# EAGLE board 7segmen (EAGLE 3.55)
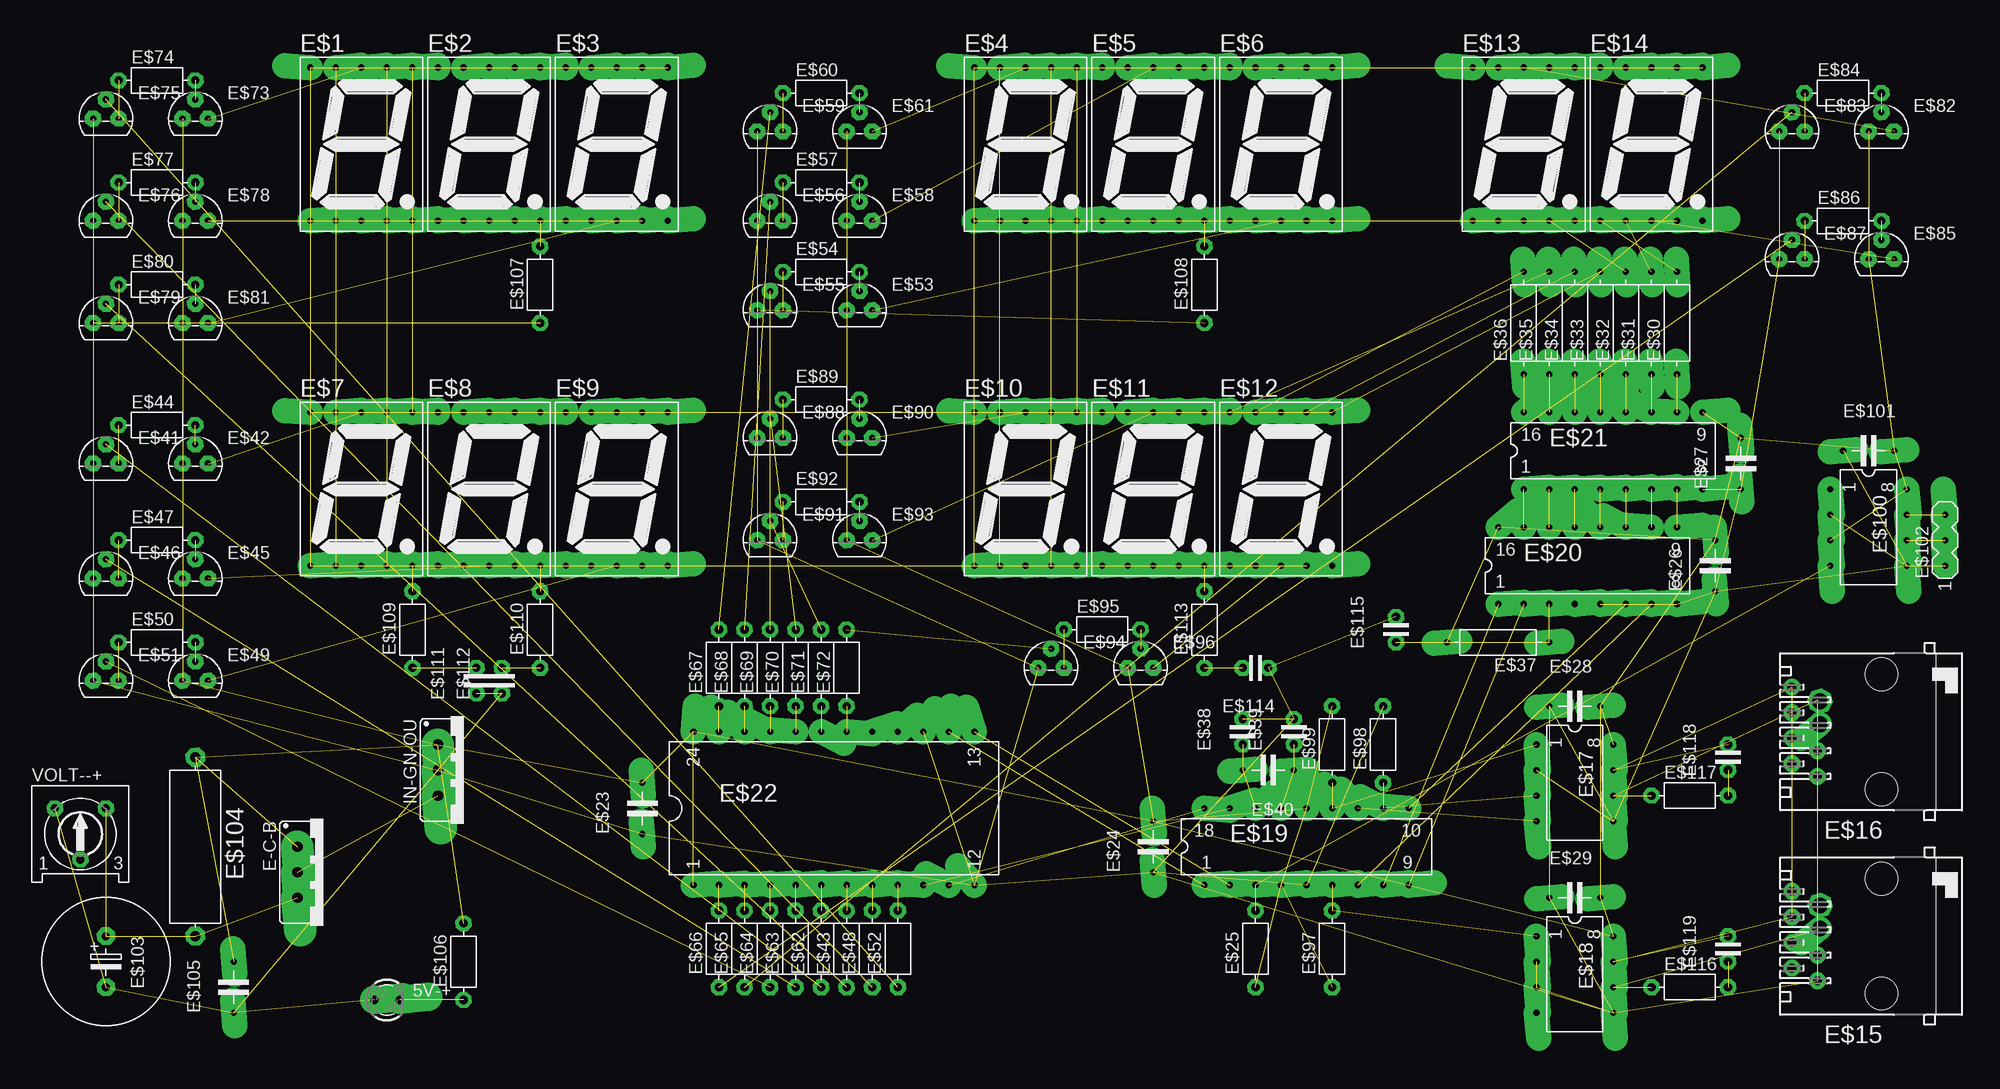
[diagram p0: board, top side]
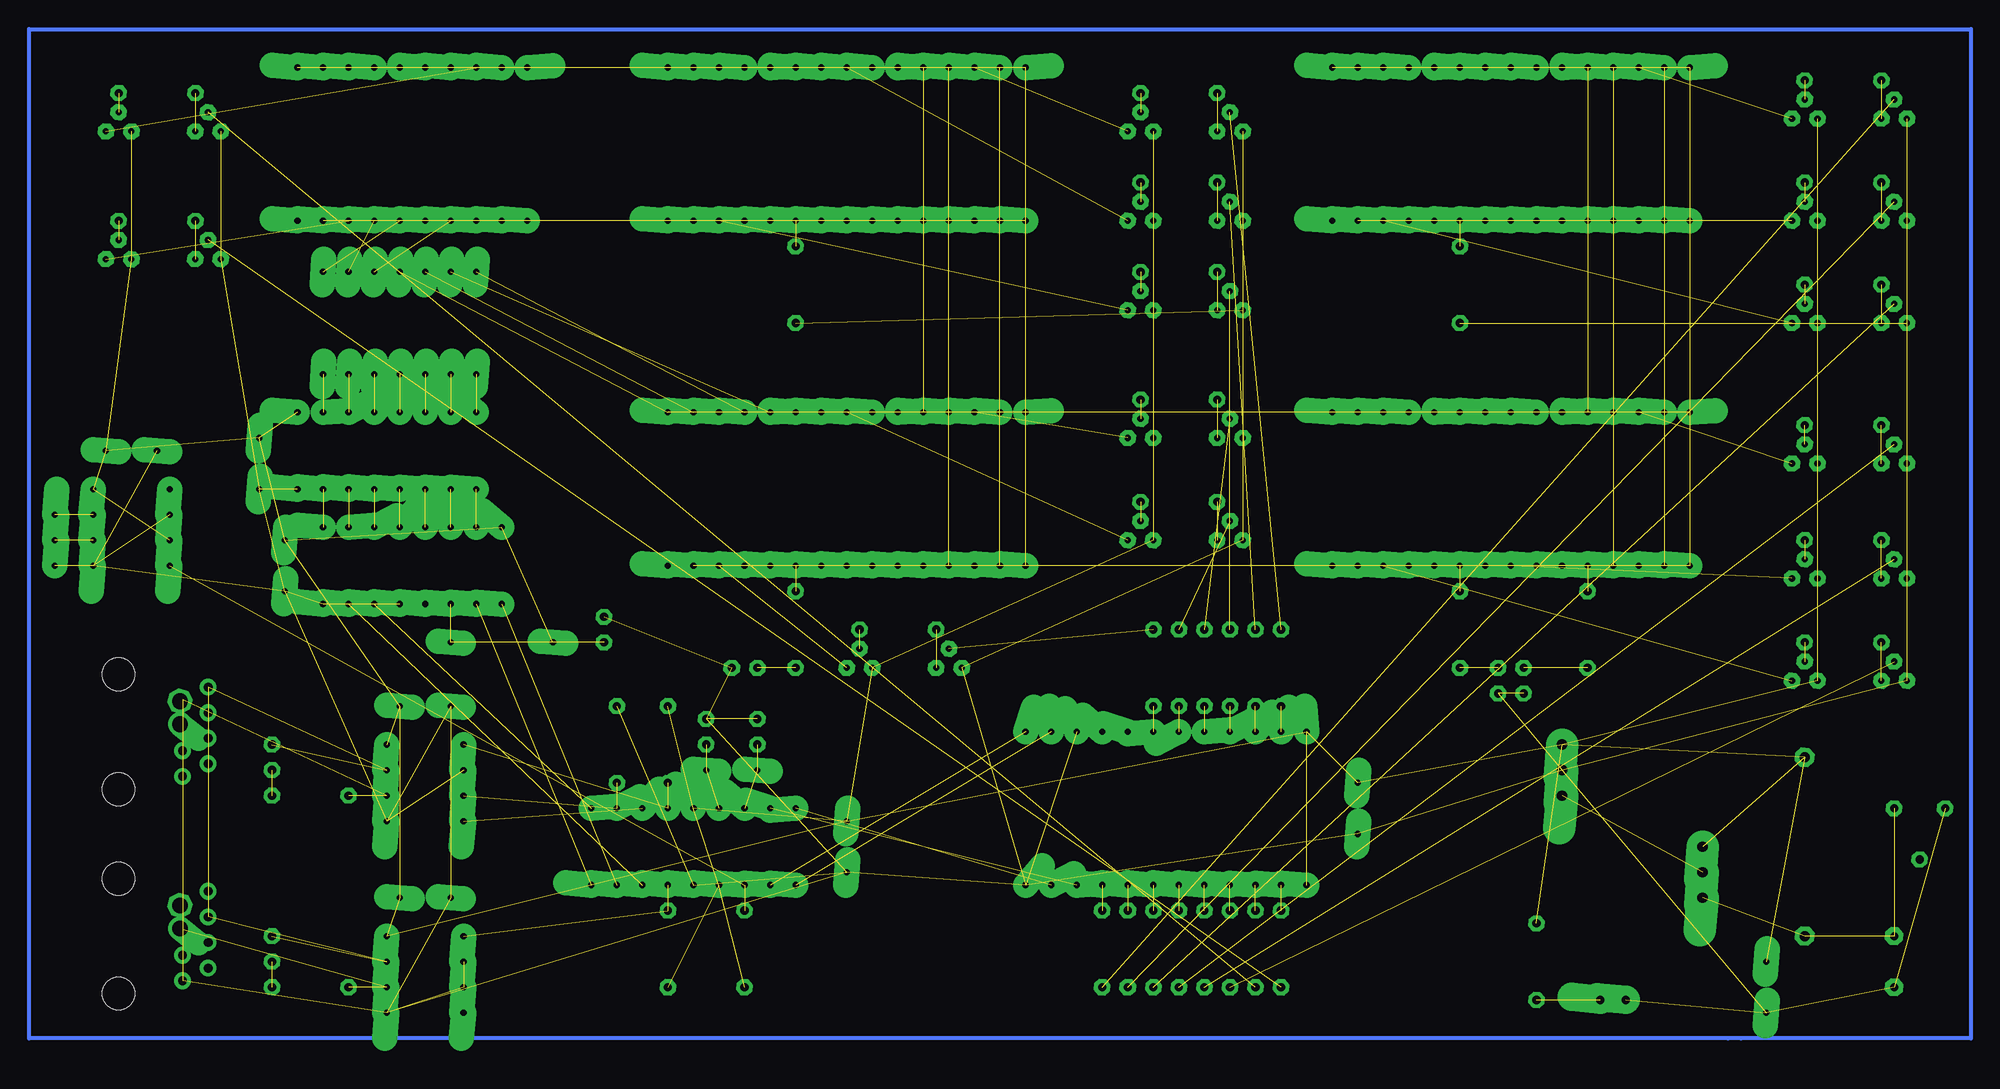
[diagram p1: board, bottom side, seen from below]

No outline drawn. Coordinates in mm, seen from the top.
Copper layers used: Bottom

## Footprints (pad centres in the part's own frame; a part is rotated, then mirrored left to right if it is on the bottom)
D3E = drill 0.813 pad 2.845 offset:  -1.27,0;  1.27,0
EG-13 = drill 0.61 pad 2.54 offset:  -5.08,-7.62;  -2.54,-7.62;  0,-7.62;  2.54,-7.62;  5.08,-7.62;  5.08,7.62;  2.54,7.62;  0,7.62;  -2.54,7.62;  -5.08,7.62
6591-1 = drill 1.575 pad 0.254 octagon:  3.048,6.096 | drill 1.575 pad 0.254 offset:  0.762,6.096 | drill 0.889 pad 1.676 round:  1.905,8.89;  0.635,6.35;  -0.635,8.89;  -1.905,6.35;  -3.175,8.89;  -4.445,6.35;  3.175,6.35;  4.445,8.89 | hole 3.251: -5.715,0; 5.715,0
L08 = drill 0.61 pad 2.54 offset:  -3.81,-3.81;  -1.27,-3.81;  1.27,-3.81;  3.81,-3.81;  3.81,3.81;  1.27,3.81;  -1.27,3.81;  -3.81,3.81
L18 = drill 0.61 pad 2.54 offset:  -10.16,-3.81;  -7.62,-3.81;  -5.08,-3.81;  -2.54,-3.81;  0,-3.81;  2.54,-3.81;  5.08,-3.81;  7.62,-3.81;  10.16,-3.81;  10.16,3.81;  7.62,3.81;  5.08,3.81;  2.54,3.81;  0,3.81;  -2.54,3.81;  -5.08,3.81;  -7.62,3.81;  -10.16,3.81
L16 = drill 0.61 pad 2.54 offset:  -8.89,-3.81;  -6.35,-3.81;  -3.81,-3.81;  -1.27,-3.81;  1.27,-3.81;  3.81,-3.81;  6.35,-3.81;  8.89,-3.81;  8.89,3.81;  6.35,3.81;  3.81,3.81;  1.27,3.81;  -1.27,3.81;  -3.81,3.81;  -6.35,3.81;  -8.89,3.81
L24-6 = drill 0.61 pad 2.54 offset:  -13.97,-7.62;  -11.43,-7.62;  -8.89,-7.62;  -6.35,-7.62;  -3.81,-7.62;  -1.27,-7.62;  1.27,-7.62;  3.81,-7.62;  6.35,-7.62;  8.89,-7.62;  11.43,-7.62;  13.97,-7.62;  13.97,7.62;  11.43,7.62;  8.89,7.62;  6.35,7.62;  3.81,7.62;  1.27,7.62;  -1.27,7.62;  -3.81,7.62;  -6.35,7.62;  -8.89,7.62;  -11.43,7.62;  -13.97,7.62
5 = drill 0.61 pad 2.54 long:  -2.54,0;  2.54,0
7,5 = drill 0.813 pad 1.6 octagon:  -3.81,0;  3.81,0
10 = drill 0.61 pad 2.54 long:  -5.08,0;  5.08,0
2,5 = drill 0.813 pad 1.6 octagon:  -1.27,0;  1.27,0
92D = drill 0.61 pad 1.6 octagon:  -1.27,0;  0,1.905;  1.27,0
03-1 = drill 0.61 pad 2.54 offset:  -2.54,0;  0,0;  2.54,0
-5L = drill 0.813 pad 1.778 octagon:  0,0;  5.08,0
18 = drill 1.016 pad 1.905 octagon:  -8.89,0;  8.89,0
220S = drill 1.016 pad 3.251 offset:  -2.54,-2.54;  0,-2.54;  2.54,-2.54
3 = drill 0.813 pad 1.6 octagon:  -2.54,2.54;  0,-2.54;  2.54,2.54

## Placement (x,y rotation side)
5V-+  [D3E]  22.86,-10.16 0 top
E$1  [EG-13]  20.32,74.93 0 top
E$2  [EG-13]  33.02,74.93 0 top
E$3  [EG-13]  45.72,74.93 0 top
E$4  [EG-13]  86.36,74.93 0 top
E$5  [EG-13]  99.06,74.93 0 top
E$6  [EG-13]  111.76,74.93 0 top
E$7  [EG-13]  20.32,40.64 0 top
E$8  [EG-13]  33.02,40.64 0 top
E$9  [EG-13]  45.72,40.64 0 top
E$10  [EG-13]  86.36,40.64 0 top
E$11  [EG-13]  99.06,40.64 0 top
E$12  [EG-13]  111.76,40.64 0 top
E$13  [EG-13]  135.89,74.93 0 top
E$14  [EG-13]  148.59,74.93 0 top
E$15  [6591-1]  171.45,-3.81 90 top
E$16  [6591-1]  171.45,16.51 90 top
E$17  [L08]  140.97,11.43 270 top
E$18  [L08]  140.97,-7.62 270 top
E$19  [L18]  114.3,5.08 0 top
E$20  [L16]  142.24,33.02 0 top
E$21  [L16]  144.78,44.45 0 top
E$22  [L24-6]  67.31,8.89 0 top
E$23  [5]  48.26,8.89 90 top
E$24  [5]  99.06,5.08 90 top
E$25  [7,5]  109.22,-5.08 90 top
E$26  [5]  154.94,33.02 90 top
E$27  [5]  157.48,43.18 90 top
E$28  [5]  140.97,19.05 0 top
E$29  [5]  140.97,0 0 top
E$30  [10]  151.13,57.15 90 top
E$31  [10]  148.59,57.15 90 top
E$32  [10]  146.05,57.15 90 top
E$33  [10]  143.51,57.15 90 top
E$34  [10]  140.97,57.15 90 top
E$35  [10]  138.43,57.15 90 top
E$36  [10]  135.89,57.15 90 top
E$37  [10]  133.35,25.4 180 top
E$38  [2,5]  107.95,16.51 90 top
E$39  [2,5]  113.03,16.51 90 top
E$40  [5]  110.49,12.7 180 top
E$41  [92D]  -5.08,43.18 0 top
E$42  [92D]  3.81,43.18 0 top
E$43  [7,5]  68.58,-5.08 90 top
E$44  [7,5]  0,46.99 0 top
E$45  [92D]  3.81,31.75 0 top
E$46  [92D]  -5.08,31.75 0 top
E$47  [7,5]  0,35.56 0 top
E$48  [7,5]  71.12,-5.08 90 top
E$49  [92D]  3.81,21.59 0 top
E$50  [7,5]  0,25.4 0 top
E$51  [92D]  -5.08,21.59 0 top
E$52  [7,5]  73.66,-5.08 90 top
E$53  [92D]  69.85,58.42 0 top
E$54  [7,5]  66.04,62.23 0 top
E$55  [92D]  60.96,58.42 0 top
E$56  [92D]  60.96,67.31 0 top
E$57  [7,5]  66.04,71.12 0 top
E$58  [92D]  69.85,67.31 0 top
E$59  [92D]  60.96,76.2 0 top
E$60  [7,5]  66.04,80.01 0 top
E$61  [92D]  69.85,76.2 0 top
E$62  [7,5]  66.04,-5.08 90 top
E$63  [7,5]  63.5,-5.08 90 top
E$64  [7,5]  60.96,-5.08 90 top
E$65  [7,5]  58.42,-5.08 90 top
E$66  [7,5]  55.88,-5.08 90 top
E$67  [7,5]  55.88,22.86 90 top
E$68  [7,5]  58.42,22.86 90 top
E$69  [7,5]  60.96,22.86 90 top
E$70  [7,5]  63.5,22.86 90 top
E$71  [7,5]  66.04,22.86 90 top
E$72  [7,5]  68.58,22.86 90 top
E$73  [92D]  3.81,77.47 0 top
E$74  [7,5]  0,81.28 0 top
E$75  [92D]  -5.08,77.47 0 top
E$76  [92D]  -5.08,67.31 0 top
E$77  [7,5]  0,71.12 0 top
E$78  [92D]  3.81,67.31 0 top
E$79  [92D]  -5.08,57.15 0 top
E$80  [7,5]  0,60.96 0 top
E$81  [92D]  3.81,57.15 0 top
E$82  [92D]  171.45,76.2 0 top
E$83  [92D]  162.56,76.2 0 top
E$84  [7,5]  167.64,80.01 0 top
E$85  [92D]  171.45,63.5 0 top
E$86  [7,5]  167.64,67.31 0 top
E$87  [92D]  162.56,63.5 0 top
E$88  [92D]  60.96,45.72 0 top
E$89  [7,5]  66.04,49.53 0 top
E$90  [92D]  69.85,45.72 0 top
E$91  [92D]  60.96,35.56 0 top
E$92  [7,5]  66.04,39.37 0 top
E$93  [92D]  69.85,35.56 0 top
E$94  [92D]  88.9,22.86 0 top
E$95  [7,5]  93.98,26.67 0 top
E$96  [92D]  97.79,22.86 0 top
E$97  [7,5]  116.84,-5.08 90 top
E$98  [7,5]  121.92,15.24 90 top
E$99  [7,5]  116.84,15.24 90 top
E$100  [L08]  170.18,36.83 270 top
E$101  [5]  170.18,44.45 0 top
E$102  [03-1]  177.8,35.56 90 top
E$103  [-5L]  -5.08,-3.81 270 top
E$104  [18]  3.81,5.08 270 top
E$105  [5]  7.62,-8.89 90 top
E$106  [7,5]  30.48,-6.35 90 top
E$107  [7,5]  38.1,60.96 90 top
E$108  [7,5]  104.14,60.96 90 top
E$109  [7,5]  25.4,26.67 90 top
E$110  [7,5]  38.1,26.67 90 top
E$111  [2,5]  31.75,21.59 90 top
E$112  [2,5]  34.29,21.59 90 top
E$113  [7,5]  104.14,26.67 90 top
E$114  [2,5]  109.22,22.86 180 top
E$115  [2,5]  123.19,26.67 90 top
E$116  [7,5]  152.4,-8.89 0 top
E$117  [7,5]  152.4,10.16 0 top
E$118  [2,5]  156.21,13.97 90 top
E$119  [2,5]  156.21,-5.08 90 top
E-C-B  [220S]  16.51,2.54 270 top
IN-GN-OU  [220S]  30.48,12.7 270 top
VOLT--+  [3]  -7.62,6.35 0 top

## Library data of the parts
5V-+ = led
E$1-E$14 = special
E$15 E$16 = amp-j
E$17-E$22 E$100 = 74xx
E$23-E$40 E$43 E$44 E$47 E$48 E$50 E$52 E$54 E$57 E$60 E$62-E$72 E$74 E$77 E$80 E$84 E$86 E$89 E$92 E$95 E$97-E$99 E$101 E$103-E$119 = discrete
E$41 E$42 E$45 E$46 E$49 E$51 E$53 E$55 E$56 E$58 E$59 E$61 E$73 E$75 E$76 E$78 E$79 E$81-E$83 E$85 E$87 E$88 E$90 E$91 E$93 E$94 E$96 = trans-sm
E$102 = con-lstb
E-C-B IN-GN-OU = v-reg
VOLT--+ = trimpot

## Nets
S$2: E$1. E$2. E$3. E$4. E$5. E$6. E$7. E$8. E$9. E$10. E$11. E$12. E$13. E$14. E$30.
S$3: E$1. E$2. E$3. E$4. E$5. E$6. E$7. E$8. E$9. E$10. E$11. E$12. E$13. E$14. E$32.
S$4: E$21. E$36.
S$5: E$21. E$35.
S$6: E$21. E$34.
S$7: E$21. E$33.
S$8: E$21. E$32.
S$9: E$21. E$31.
S$10: E$1. E$2. E$3. E$4. E$5. E$6. E$7. E$8. E$9. E$10. E$11. E$12. E$13. E$14. E$31.
S$11: E$1. E$2. E$3. E$4. E$5. E$6. E$7. E$8. E$9. E$10. E$11. E$12. E$13. E$14. E$33.
S$12: E$21. E$30.
S$14: E$1. E$2. E$3. E$4. E$5. E$6. E$7. E$8. E$9. E$10. E$11. E$12. E$13. E$14. E$34.
S$16: E$19. E$20.
S$17: E$19. E$20.
S$18: E$19. E$20.
S$19: E$1. E$2. E$3. E$4. E$5. E$6. E$7. E$8. E$9. E$10. E$11. E$12. E$13. E$14. E$36.
S$20: E$19. E$20.
S$22: E$20. E$37. E$115.
S$24: E$1. E$2. E$3. E$4. E$5. E$6. E$7. E$8. E$9. E$10. E$11. E$12. E$13. E$14. E$35.
S$25: E$19. E$25. E$100.
S$28: E$19. E$22.
S$29: E$20. E$21.
S$30: E$20. E$21.
S$31: E$20. E$21.
S$32: E$20. E$21.
S$33: E$20. E$21.
S$34: E$20. E$21.
S$35: E$20. E$21.
S$36: E$19. E$22.
S$37: E$19. E$22.
S$38: E$19. E$22.
S$39: E$19. E$38. E$40.
S$40: E$19. E$39. E$40.
S$44: E$18. E$19. E$97.
S$45: E$17. E$19. E$99.
S$46: E$17. E$19. E$98.
S$47: E$22. E$67.
S$48: E$22. E$68.
S$49: E$22. E$69.
S$50: E$22. E$70.
S$51: E$22. E$71.
S$52: E$22. E$72.
S$53: E$22. E$66.
S$54: E$22. E$65.
S$55: E$22. E$64.
S$56: E$22. E$63.
S$57: E$22. E$62.
S$58: E$22. E$43.
S$59: E$22. E$48.
S$60: E$22. E$52.
S$62: E$100. E$102.
S$64: E$100. E$102.
S$65: E$15. E$16. E$18. E$119.
S$66: E$17. E$19.
S$69: E$15. E$16. E$18. E$116.
S$70: E$15. E$16. E$17. E$118.
S$71: E$15. E$16. E$17. E$117.
S$72: E$74. E$75.
S$73: E$73. E$74.
S$74: E$76. E$77.
S$75: E$77. E$78.
S$76: E$79. E$80.
S$77: E$80. E$81.
S$78: E$41. E$44.
S$79: E$42. E$44.
S$80: E$46. E$47.
S$81: E$45. E$47.
S$82: E$50. E$51.
S$83: E$49. E$50.
S$84: E$59. E$60.
S$85: E$60. E$61.
S$86: E$56. E$57.
S$87: E$57. E$58.
S$88: E$54. E$55.
S$89: E$53. E$54.
S$90: E$88. E$89.
S$91: E$89. E$90.
S$92: E$91. E$92.
S$93: E$92. E$93.
S$94: E$94. E$95.
S$95: E$95. E$96.
S$96: E$83. E$84.
S$97: E$82. E$84.
S$98: E$86. E$87.
S$99: E$85. E$86.
S$100: 5V-+. E$15. E$16. E$17. E$18. E$19. E$20. E$21. E$22. E$23. E$24. E$26. E$27. E$28. E$29. E$38. E$39. E$41. E$46. E$51. E$55. E$56. E$59. E$75. E$76. E$79. E$83. E$87. E$88. E$91. E$94. E$98. E$100. E$101. E$102. E$103. E$105. E$107. E$108. E$111. E$112. E$114. E$115. IN-GN-OU. VOLT--+.
S$101: E$17. E$18. E$19. E$20. E$21. E$22. E$23. E$24. E$25. E$26. E$27. E$28. E$29. E$37. E$42. E$45. E$49. E$53. E$58. E$61. E$73. E$78. E$81. E$82. E$85. E$90. E$93. E$96. E$97. E$99. E$100. E$101. E$104. E$105. E$106. E-C-B. IN-GN-OU.
S$106: E$52. E$75.
S$107: E$48. E$76.
S$108: E$43. E$79.
S$109: E$41. E$62.
S$110: E$46. E$63.
S$111: E$51. E$64.
S$112: E$65. E$83.
S$113: E$66. E$87.
S$114: E$59. E$67.
S$115: E$56. E$68.
S$116: E$55. E$69.
S$117: E$70. E$88.
S$118: E$71. E$91.
S$119: E$72. E$94.
S$120: E$1. E$73.
S$121: E$2. E$78.
S$122: E$3. E$81.
S$123: E$7. E$42.
S$124: E$8. E$45.
S$125: E$9. E$49.
S$126: E$4. E$61.
S$127: E$5. E$58.
S$128: E$6. E$53.
S$129: E$10. E$90.
S$130: E$11. E$93.
S$131: E$12. E$96.
S$132: E$13. E$82.
S$133: E$14. E$85.
S$134: E$103. E$104. E-C-B. VOLT--+.
S$137: E-C-B. IN-GN-OU.
S$138: 5V-+. E$106.
S$139: E$2. E$107.
S$140: E$5. E$108.
S$141: E$7. E$109.
S$142: E$8. E$110.
S$143: E$109. E$111.
S$144: E$110. E$112.
S$146: E$11. E$113.
S$147: E$113. E$114.
S$148: E$117. E$118.
S$149: E$116. E$119.

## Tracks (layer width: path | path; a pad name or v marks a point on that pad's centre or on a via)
S$1
  Bottom 0.406: 10.16,-13.97 11.43,-13.97 | 11.43,-13.97 180.34,-13.97 180.34,86.36 -12.7,86.36 -12.7,-13.97 11.43,-13.97
S$2  (14 unrouted)
S$3  (14 unrouted)
S$4  (1 unrouted)
S$5  (1 unrouted)
S$6  (1 unrouted)
S$7  (1 unrouted)
S$8  (1 unrouted)
S$9  (1 unrouted)
S$10  (14 unrouted)
S$11  (14 unrouted)
S$12  (1 unrouted)
S$14  (14 unrouted)
S$16  (1 unrouted)
S$17  (1 unrouted)
S$18  (1 unrouted)
S$19  (14 unrouted)
S$20  (1 unrouted)
S$22  (2 unrouted)
S$24  (14 unrouted)
S$25  (2 unrouted)
S$28  (1 unrouted)
S$29  (1 unrouted)
S$30  (1 unrouted)
S$31  (1 unrouted)
S$32  (1 unrouted)
S$33  (1 unrouted)
S$34  (1 unrouted)
S$35  (1 unrouted)
S$36  (1 unrouted)
S$37  (1 unrouted)
S$38  (1 unrouted)
S$39  (2 unrouted)
S$40  (2 unrouted)
S$44  (2 unrouted)
S$45  (2 unrouted)
S$46  (2 unrouted)
S$47  (1 unrouted)
S$48  (1 unrouted)
S$49  (1 unrouted)
S$50  (1 unrouted)
S$51  (1 unrouted)
S$52  (1 unrouted)
S$53  (1 unrouted)
S$54  (1 unrouted)
S$55  (1 unrouted)
S$56  (1 unrouted)
S$57  (1 unrouted)
S$58  (1 unrouted)
S$59  (1 unrouted)
S$60  (1 unrouted)
S$62  (1 unrouted)
S$64  (1 unrouted)
S$65  (3 unrouted)
S$66  (1 unrouted)
S$69  (3 unrouted)
S$70  (3 unrouted)
S$71  (3 unrouted)
S$72  (1 unrouted)
S$73  (1 unrouted)
S$74  (1 unrouted)
S$75  (1 unrouted)
S$76  (1 unrouted)
S$77  (1 unrouted)
S$78  (1 unrouted)
S$79  (1 unrouted)
S$80  (1 unrouted)
S$81  (1 unrouted)
S$82  (1 unrouted)
S$83  (1 unrouted)
S$84  (1 unrouted)
S$85  (1 unrouted)
S$86  (1 unrouted)
S$87  (1 unrouted)
S$88  (1 unrouted)
S$89  (1 unrouted)
S$90  (1 unrouted)
S$91  (1 unrouted)
S$92  (1 unrouted)
S$93  (1 unrouted)
S$94  (1 unrouted)
S$95  (1 unrouted)
S$96  (1 unrouted)
S$97  (1 unrouted)
S$98  (1 unrouted)
S$99  (1 unrouted)
S$100  (50 unrouted)
S$101  (39 unrouted)
S$106  (1 unrouted)
S$107  (1 unrouted)
S$108  (1 unrouted)
S$109  (1 unrouted)
S$110  (1 unrouted)
S$111  (1 unrouted)
S$112  (1 unrouted)
S$113  (1 unrouted)
S$114  (1 unrouted)
S$115  (1 unrouted)
S$116  (1 unrouted)
S$117  (1 unrouted)
S$118  (1 unrouted)
S$119  (1 unrouted)
S$120  (1 unrouted)
S$121  (1 unrouted)
S$122  (1 unrouted)
S$123  (1 unrouted)
S$124  (1 unrouted)
S$125  (1 unrouted)
S$126  (1 unrouted)
S$127  (1 unrouted)
S$128  (1 unrouted)
S$129  (1 unrouted)
S$130  (1 unrouted)
S$131  (1 unrouted)
S$132  (1 unrouted)
S$133  (1 unrouted)
S$134  (3 unrouted)
S$137  (1 unrouted)
S$138  (1 unrouted)
S$139  (1 unrouted)
S$140  (1 unrouted)
S$141  (1 unrouted)
S$142  (1 unrouted)
S$143  (1 unrouted)
S$144  (1 unrouted)
S$146  (1 unrouted)
S$147  (1 unrouted)
S$148  (1 unrouted)
S$149  (1 unrouted)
